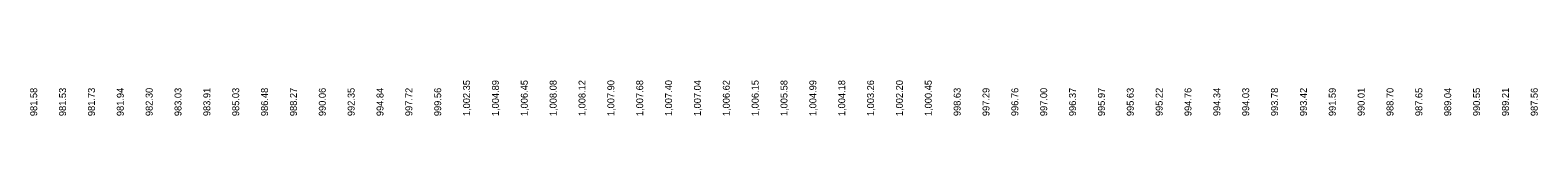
# Model space of a CAD drawing. Extents: x 16972137 to 16976737, y 12558490 to 12559551.
# Drawn here: x 16972137 to 16973443, y 12558490 to 12558520 of the extents above; entities that cross this region are included whole.
import ezdxf

# ---------------------------------------------------------------- set-up
doc = ezdxf.new("R2010")
doc.units = 0
doc.layers.add('RD_DDB_StripGrade_PR', color=7, linetype='Continuous')

msp = doc.modelspace()

# ---------------------------------------------------------------- texts
at = {"layer": 'RD_DDB_StripGrade_PR'}
for s, p in [('1,002.35', (16972517.9, 12558489.3)), ('1,004.89', (16972542.9, 12558489.3)), ('1,006.45', (16972567.9, 12558489.3)), ('1,008.08', (16972592.9, 12558489.3)), ('1,008.12', (16972617.9, 12558489.3)), ('1,007.90', (16972642.9, 12558489.3)), ('1,007.68', (16972667.9, 12558489.3)), ('1,007.40', (16972692.9, 12558489.3)), ('1,007.04', (16972717.9, 12558489.3)), ('1,006.62', (16972742.9, 12558489.3)), ('1,006.15', (16972767.9, 12558489.3)), ('1,005.58', (16972792.9, 12558489.3)), ('1,004.99', (16972817.9, 12558489.3)), ('1,004.18', (16972842.9, 12558489.3)), ('1,003.26', (16972867.9, 12558489.3)), ('1,002.20', (16972892.9, 12558489.3)), ('1,000.45', (16972917.9, 12558489.3)), ('981.58', (16972142.9, 12558489.3)), ('981.53', (16972167.9, 12558489.3)), ('981.73', (16972192.9, 12558489.3)), ('981.94', (16972217.9, 12558489.3)), ('982.30', (16972242.9, 12558489.3)), ('983.03', (16972267.9, 12558489.3)), ('983.91', (16972292.9, 12558489.3)), ('985.03', (16972317.9, 12558489.3)), ('986.48', (16972342.9, 12558489.3)), ('988.27', (16972367.9, 12558489.3)), ('990.06', (16972392.9, 12558489.3)), ('992.35', (16972417.9, 12558489.3)), ('994.84', (16972442.9, 12558489.3)), ('997.72', (16972467.9, 12558489.3)), ('999.56', (16972492.9, 12558489.3)), ('998.63', (16972942.9, 12558489.3)), ('997.29', (16972967.9, 12558489.3)), ('996.76', (16972992.9, 12558489.3)), ('997.00', (16973017.9, 12558489.3)), ('996.37', (16973042.9, 12558489.3)), ('995.97', (16973067.9, 12558489.3)), ('995.63', (16973092.9, 12558489.3)), ('995.22', (16973117.9, 12558489.3)), ('994.76', (16973142.9, 12558489.3)), ('994.34', (16973167.9, 12558489.3)), ('994.03', (16973192.9, 12558489.3)), ('993.78', (16973217.9, 12558489.3)), ('993.42', (16973242.9, 12558489.3)), ('991.59', (16973267.9, 12558489.3)), ('990.01', (16973292.9, 12558489.3)), ('988.70', (16973317.9, 12558489.3)), ('987.65', (16973342.9, 12558489.3)), ('989.04', (16973367.9, 12558489.3)), ('990.55', (16973392.9, 12558489.3)), ('989.21', (16973417.9, 12558489.3)), ('987.56', (16973442.9, 12558489.3))]:
    msp.add_text(s, height=6, rotation=90, dxfattribs=at).set_placement(p)

doc.saveas('drawing.dxf')
